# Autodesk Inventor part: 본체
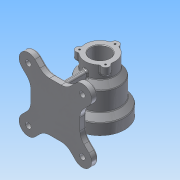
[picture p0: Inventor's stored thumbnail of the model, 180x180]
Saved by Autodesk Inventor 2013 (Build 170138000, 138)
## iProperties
Created: 2017-03
Part Number: 본체
Material: 알루미늄 6061
Document SubType Name: Modeling
Designer: Administrator
Density: 2.71 g/cm^3
Mass: 1008.36 g
Surface Area: 841.605 cm^2
Volume: 372.09 cm^3
Author: Administrator
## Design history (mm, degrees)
sketch "스케치1"
  geometry: L1 (0, 50)-(0, -50); L2 (0, -50)-(45, -50); L3 (45, -50)-(45, -30); L4 (45, -30)-(36, -19); L5 (36, -19)-(36, 15); L6 (36, 15)-(27.5, 27); L7 (27.5, 27)-(27.5, 50); L8 (27.5, 50)-(0, 50); 1 further point
  constraints: 16 end point, 3 parallel, 2 perpendicular, 1 midpoint, 1 vertical
  dimensions: "d0" = 100 distance of L1.start L1.end; "d2" = 90 diameter of L3 L1; "d3" = 72 diameter of L5 L1; "d4" = 55 diameter of L7 L1; "d5" = 65 distance from line of L5.end L2; "d6" = 20 distance of L2.end L3.end; "d7" = 31 vertical distance of L4.end L2.end; "d8" = 23 distance from line of L8 L6.end; "d9" = 50 distance from line of point (0, 0) L8
revolve "회전1" sketch "스케치1" stored, may be unused: angle "d10" = 90 deg
fillet "모깎기1" dims "d11" = 3
node "작업 평면1"
sketch "스케치2"
  geometry: L1 (-45, 45)-(45, 45); L2 (45, 45)-(45, -45); L3 (45, -45)-(-45, -45); L4 (-45, -45)-(-45, 45); L5 (-45, 45)-(45, -45); L6 (45, 45)-(-45, -45); L7 (49.497, 49.497)-(45, 45); L8 (20.958, 45)-(37.477, 61.518); L9 (45, 20.958)-(61.518, 37.477); A1 r 70 centre (0, 0) between (49.497, 49.497) and (36.106, 59.97); A2 r 17 centre (49.497, 49.497) between (59.97, 36.106) and (36.106, 59.97); 3 further points
  constraints: 18 end point, 7 point on circle, 5 midpoint, 4 parallel, 2 centre point, 2 coincident, 2 point on line, 1 collinear, 1 horizontal, 1 perpendicular
  dimensions: "d13" = 90 distance of L1.end L2.end; "d15" = 90 distance of L2.end L3.end; "d16" = 140 diameter of A1; "d17" = 34 diameter of A2; "d21" = 34 distance between parallel lines of L9 L8; "d22" = 17 distance between parallel lines of L7 L8
extrude "돌출1" join sketch "스케치2" distance "d23" = 12; taper "d24" = 0 deg
extrude "돌출2" join sketch "스케치2" distance "d25" = 12; taper "d26" = 0 deg
sketch "스케치3"
  geometry: C1 r 5 at (-49.497, -49.497); A1 r 17 centre (-49.497, -49.497) between (-61.518, -37.477) and (-37.477, -61.518) reference; 1 further point
  constraints: 1 centre point, 1 coincident
  dimensions: "d31" = 10 diameter of C1
extrude "돌출3" cut sketch "스케치3" distance "d33" = 12; taper "d34" = 0 deg
fillet "모깎기2" dims "d30" = 25
fillet "모깎기3" dims "d35" = 3
sketch "스케치4"
  geometry: L1 (4, -37)-(-4, -37); L2 (-4, -37)-(-4, 37); L3 (-4, 37)-(4, 37); L4 (4, 37)-(4, -37); L5 (4, -37)-(-4, 37); L6 (-4, -37)-(4, 37); 3 further points
  constraints: 12 end point, 3 midpoint, 2 parallel, 1 coincident, 1 horizontal, 1 perpendicular
  dimensions: "d36" = 37 distance from line of L3 point (0, 0); "d37" = 8 distance of L2.end L3.end
extrude "돌출4" join sketch "스케치4" stored distance "d38" = 12; taper "d39" = 0 deg
sketch "스케치5"
  geometry: L1 (-18.265, -31.807)-(-25, -70); L2 (-39.598, -70)-(-30.402, -70) reference; A1 r 36.678 centre (0, 0) between (4, -36.459) and (-4, -36.459) reference; 1 further point
  constraints: 2 end point, 1 point on circle, 1 point on line
  dimensions: "d40" = 25 horizontal distance of point (0, 0) L1.end; "d41" = 100 deg angle of L2 L1
feature "리브1" sketch "스케치5" dims "d42" = 1, "d43" = 8, "d44" = 0, "d45" = 0, "d46" = 1, "d47" = 1
fillet "모깎기4" dims "d48" = 3
fillet "모깎기5" dims "d49" = 3
sketch "스케치6"
  geometry: L1 (35, -50)-(35, -27); L2 (35, -27)-(26, -27); L3 (26, -27)-(26, 20); L4 (26, 20)-(17.5, 20); L5 (17.5, 20)-(17.5, 50); L6 (-45, -50)-(45, -50) reference; L7 (-27.5, 50)-(27.5, 50) reference; L8 (0, -50)-(0, 50); L9 (35, -50)-(0, -50); L10 (17.5, 50)-(0, 50); 1 further point
  constraints: 16 end point, 3 parallel, 2 midpoint, 2 point on line, 1 collinear, 1 horizontal, 1 perpendicular, 1 vertical
  dimensions: "d50" = 23 distance of L1.start L1.end; "d52" = 47 distance of L2.end L3.end; "d53" = 70 diameter of L1 L8; "d54" = 52 diameter of L3 L8; "d55" = 35 diameter of L5 L8
revolve "회전2" sketch "스케치6" stored, may be unused: angle "d56" = 90 deg
chamfer "모따기1" distance "d57" = 1; stored, may be unused: second distance "d58" = 2, angle "d59" = 45 deg
fillet "모깎기6" dims "d60" = 3
sketch "스케치7" dims "d61" = 80
  geometry: C1 r 45 at (0, 0) reference; 2 further points
  constraints: 2 vertical alignment, 1 coincident, 2 other
hole "구멍1" sketch "스케치7" at (0, 40) diameter "d63" = 3.242; stored, may be unused: countersink angle "d67" = 90 deg, drill point angle "d69" = 118 deg; dims "d64" = 9, "d65" = 4, "d66" = 2, "d68" = 11
sketch "스케치8"
  geometry: C1 r 7 at (0, 27.5); 1 further point
  constraints: 2 vertical alignment, 1 centre point, 1 other
  dimensions: "d73" = 14 diameter of C1
extrude "돌출5" join sketch "스케치8" distance "d75" = 15; taper "d76" = 0 deg
fillet "모깎기7" dims "d77" = 3
hole "구멍2" diameter "d80" = 3.242; stored, may be unused: countersink angle "d84" = 90 deg, drill point angle "d86" = 118 deg; dims "d78" = 10, "d79" = 10, "d81" = 9, "d82" = 4, "d83" = 2, "d85" = 11
node "작업 평면2"
sketch "스케치9"
  geometry: C1 r 5 at (0, 0); 1 further point
  constraints: 1 centre point, 1 coincident
  dimensions: "d91" = 10 diameter of C1
extrude "돌출6" join sketch "스케치9" stored distance "d93" = 15; taper "d94" = 0 deg
fillet "모깎기8" dims "d95" = 3
hole "구멍3" diameter "d98" = 4.134; stored, may be unused: countersink angle "d102" = 90 deg, drill point angle "d104" = 118 deg; dims "d96" = 10, "d97" = 10, "d99" = 9, "d100" = 4, "d101" = 2, "d103" = 34
sketch "스케치10"
  geometry: 2 further points
  constraints: 1 horizontal alignment, 1 other
  dimensions: "d105" = 35 distance of point (0, 0) point (-35, 0)
feature "엠보싱1" sketch "스케치10" dims "d13" = 90, "d15" = 90, "d16" = 140, "d17" = 34, "d21" = 34, "d22" = 17, "d106" = 0.5, "d107" = 0
node "솔리드1"
pattern_circular "원형 패턴1" dims angle "d28" = 360 deg
mirror "대칭1"
pattern_circular "원형 패턴2" dims angle "d71" = 360 deg
pattern_circular "원형 패턴3" dims "d88" = 360 deg
other parameters: "d12" = -82
